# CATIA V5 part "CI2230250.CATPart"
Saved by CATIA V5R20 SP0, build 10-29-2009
Part number: CI2230250
Bounding box of the stored display mesh (mm): x -29 to 29, y -23.836 to 295, z -41.554 to 32.071
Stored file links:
  C:\Users\Raffaele\Desktop\3D X SITO CF\BOLEX\19-INCLINED ASSEMBLY REF_CI\CI2230250.CATPart
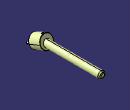
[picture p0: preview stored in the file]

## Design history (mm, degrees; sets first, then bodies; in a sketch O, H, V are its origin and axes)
Set1
  DatumSurface1 to DatumSurface16 "MANIFOLD_SOLID_BREP #399"
  DatumSurface17 to DatumSurface39 "MANIFOLD_SOLID_BREP #1173"
Body1 (main body)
